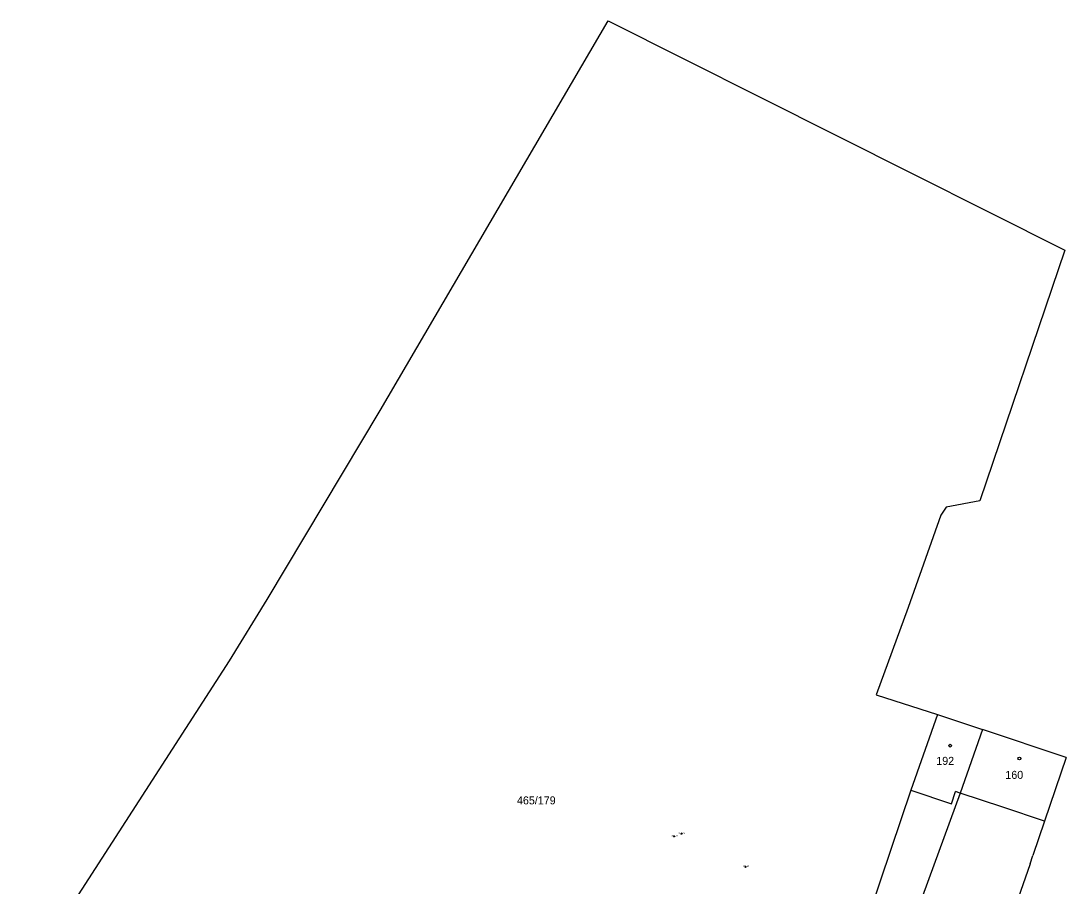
# Model space of a CAD drawing. Extents: x -643859 to -643594, y -1190913 to -1190609.
# Drawn here: x -643827 to -643696.5, y -1190717.2 to -1190609 of the extents above; entities that cross this region are included whole.
import ezdxf

# ---------------------------------------------------------------- set-up
doc = ezdxf.new("R2010")
doc.units = 0
for name, color, linetype in [('Default', 7, 'Continuous'), ('Hranice parcel', 7, 'Continuous'), ('Svodidla_zábradlí', 7, 'Continuous'), ('Vrstva 1', 7, 'Continuous'), ('Vrstva 11', 7, 'Continuous'), ('Vrstva 63', 7, 'Continuous')]:
    doc.layers.add(name, color=color, linetype=linetype)

msp = doc.modelspace()

# ---------------------------------------------------------------- linework, layer by layer
at = {"layer": 'Default'}
for centre in [(-643745.43, -1190710.95), (-643744.52, -1190710.62), (-643736.51, -1190714.76)]:
    msp.add_circle(centre, 0.0625, dxfattribs=at)
at = {"layer": 'Hranice parcel'}
for p, q in [((-643782.17, -1190657.69), (-643753.68, -1190609)), ((-643753.68, -1190609), (-643696.62, -1190637.65)), ((-643696.62, -1190637.65), (-643707.22, -1190668.98)), ((-643796.26, -1190681.32), (-643782.17, -1190657.69)), ((-643707.22, -1190668.98), (-643711.44, -1190669.8)), ((-643711.44, -1190669.8), (-643712.12, -1190670.78)), ((-643712.12, -1190670.78), (-643716.18, -1190682.34)), ((-643800.99, -1190688.99), (-643796.26, -1190681.32)), ((-643716.18, -1190682.34), (-643720.18, -1190693.25)), ((-643827.03, -1190729.39), (-643800.99, -1190688.99)), ((-643720.18, -1190693.25), (-643712.54, -1190695.69)), ((-643712.54, -1190695.69), (-643715.87, -1190705.15)), ((-643712.54, -1190695.69), (-643706.9, -1190697.6)), ((-643706.9, -1190697.6), (-643709.68, -1190705.55)), ((-643696.46, -1190701.07), (-643706.9, -1190697.6)), ((-643696.46, -1190701.07), (-643699.17, -1190709.02)), ((-643715.87, -1190705.15), (-643721.72, -1190722.62)), ((-643709.68, -1190705.55), (-643716.58, -1190724.3)), ((-643699.17, -1190709.02), (-643700.6, -1190713.33)), ((-643700.95, -1190714.38), (-643700.6, -1190713.33)), ((-643700.95, -1190714.38), (-643702.74, -1190719.49))]:
    msp.add_line(p, q, dxfattribs=at)
at = {"layer": 'Vrstva 1'}
for p, q in [((-643715.87, -1190705.15), (-643710.79, -1190706.86)), ((-643710.79, -1190706.86), (-643710.27, -1190705.35)), ((-643709.68, -1190705.55), (-643710.27, -1190705.35)), ((-643704.37, -1190707.3), (-643709.68, -1190705.55)), ((-643699.17, -1190709.02), (-643704.37, -1190707.3))]:
    msp.add_line(p, q, dxfattribs=at)
at = {"layer": 'Vrstva 11'}
for centre in [(-643710.94, -1190699.6), (-643702.3, -1190701.2)]:
    msp.add_circle(centre, 0.175, dxfattribs=at)

# ---------------------------------------------------------------- texts
at = {"layer": 'Svodidla_zábradlí'}
for s, p in [('329.86', (-643745.78, -1190710.95)), ('329.86', (-643744.87, -1190710.62)), ('329.83', (-643736.86, -1190714.76))]:
    msp.add_text(s, height=0.19, dxfattribs=at).set_placement(p)
at = {"layer": 'Vrstva 63'}
for s, p in [('192', (-643712.68, -1190702)), ('160', (-643704.05, -1190703.75)), ('465/179', (-643765.06, -1190706.94))]:
    msp.add_text(s, height=1, dxfattribs=at).set_placement(p)

doc.saveas('drawing.dxf')
